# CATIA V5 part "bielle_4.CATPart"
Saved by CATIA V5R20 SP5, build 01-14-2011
Part number: bielle_4
Bounding box of the stored display mesh (mm): x 10 to 15, y -5 to 95, z 95 to 105
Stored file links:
  U:\2A\IAO\ThinkMotion\bielle_4.CATPart
  U:\2A\IAO\ThinkMotion\MECANISME 1517.CATProduct
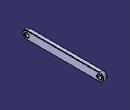
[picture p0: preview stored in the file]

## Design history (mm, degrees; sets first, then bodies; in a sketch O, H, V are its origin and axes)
Set1
  Plane1 "Plan_ref": linked copy from another document
  Point1: linked copy from another document
  Point2: linked copy from another document
Body1 (main body)
  Sketch1 on Plane1, origin (0, 0, 0), H (0, 1, 0), V (0, 0, 1)
    construction line L1 (0, 100) -> (90, 100)
    point P1 (0, 100)
    point P2 (90, 100)
    line L2 (0, 105) -> (90, 105)
    line L3 (90, 95) -> (0, 95)
    arc A1 centre (90, 100) radius 5 from (90, 105) to (90, 95) cw
    arc A2 centre (0, 100) radius 5 from (0, 95) to (0, 105) cw
    reference projected point E1 (0, 100) from Point1
    reference projected point E2 (90, 100) from Point2
    distance L1 L2 = 5
    horizontal: L1 H
    tangency: A1 L2, A2 L2, A1 L3, A2 L3
    coincidence: P1 E1, E2 P2
  Pad1: profile Sketch1, direction (1, 0, 0), length 15
  Sketch2 on start face of Pad1, origin (0, 90, 100), H (0, 1, 0), V (0, 0, -1)
    point P1 (0, 0)
    reference projected point E1 (0, 0) from Point2
    coincidence: E1 P1
  Hole1: placed by Sketch2, at (0, 90, 100) direction (1, 0, 0), diameter 5, through (limit type 3)
  Sketch3 on start face of Pad1, origin (0, 0, 100), H (0, 1, 0), V (0, 0, -1)
    point P1 (0, 0)
    reference projected point E1 (0, 0) from Point1
    coincidence: E1 P1
  Hole2: placed by Sketch3, at (0, 0, 100) direction (1, 0, 0), diameter 5, through (limit type 3)
  Sketch4 on Plane1, origin (0, 0, 0), H (0, 1, 0), V (0, 0, 1)
    construction line L1 (0, 100) -> (90, 100)
    point P1 (0, 100)
    point P2 (90, 100)
    line L2 (0, 105) -> (90, 105)
    line L3 (90, 95) -> (0, 95)
    arc A1 centre (90, 100) radius 5 from (90, 105) to (90, 95) cw
    arc A2 centre (0, 100) radius 5 from (0, 95) to (0, 105) cw
    reference projected point E1 (90, 100) from Point2
    reference projected point E2 (0, 100) from Point1
    distance L1 L2 = 5
    tangency: A1 L2, A2 L2, A1 L3, A2 L3
    coincidence: P2 E1, P1 E2
  Pocket1: profile Sketch4, direction (1, 0, 0), length 10
  Fillet1: radius 0.5, on end face of Pad1; end face of Pocket1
